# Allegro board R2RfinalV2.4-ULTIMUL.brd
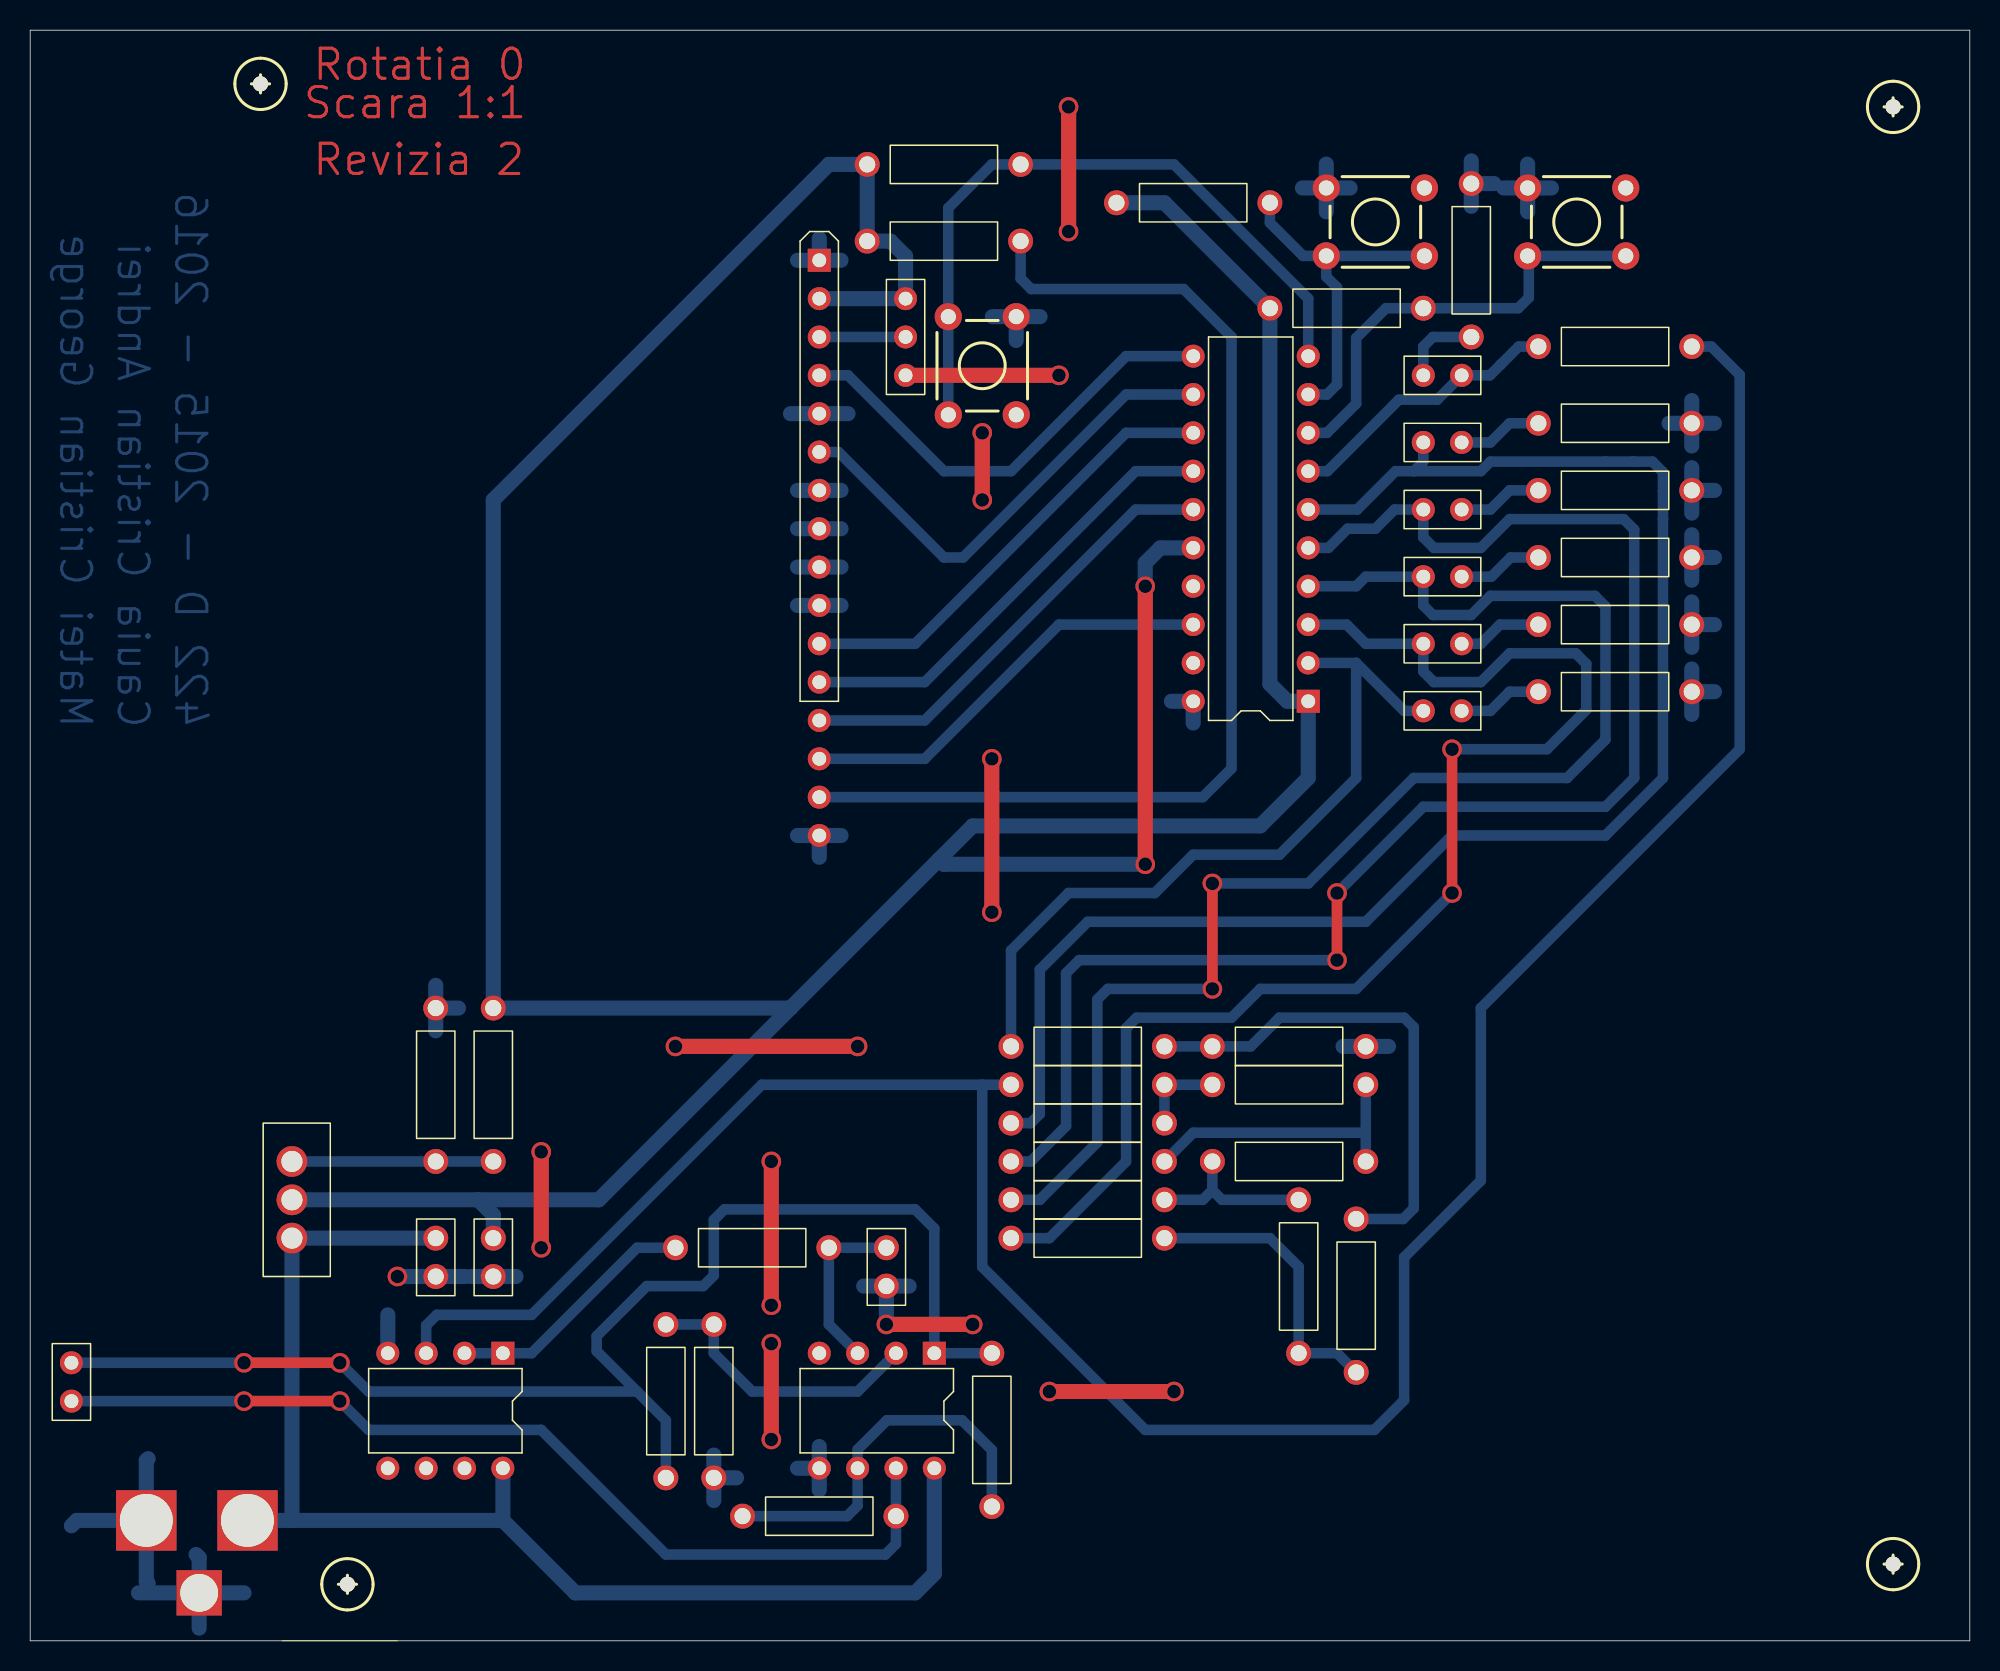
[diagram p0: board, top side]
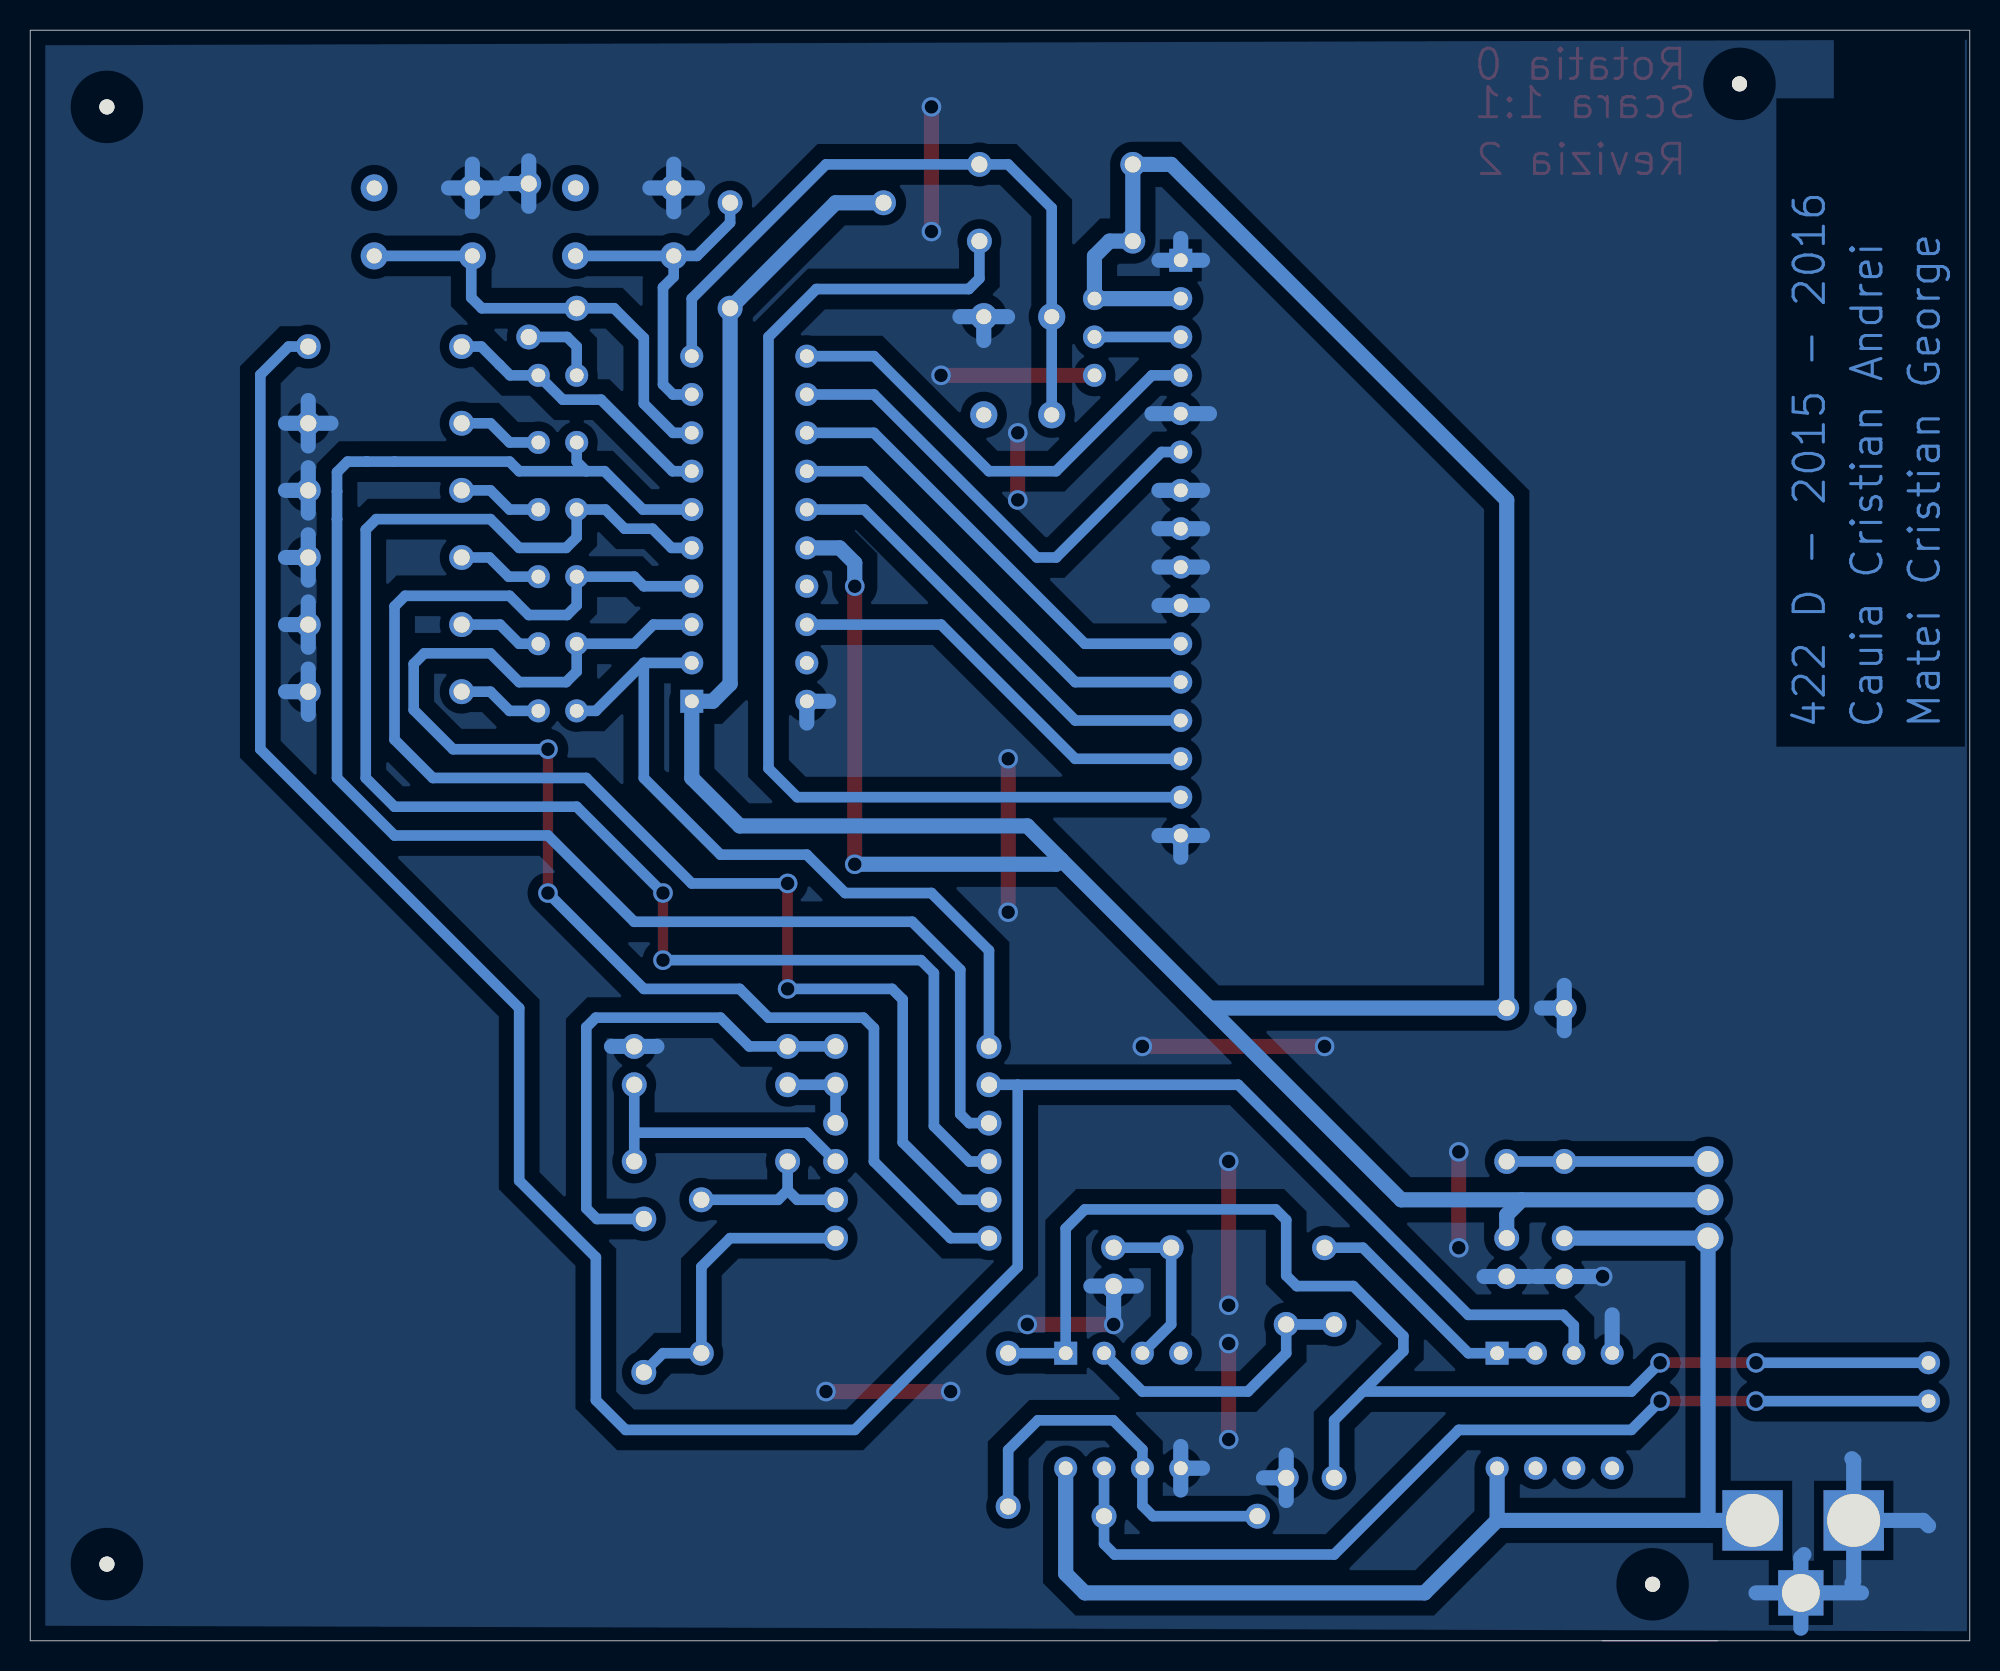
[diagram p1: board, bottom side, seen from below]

Outline 128.46 x 106.68 mm; copper layers: TOP, BOTTOM. Coordinates in mm from the lower left corner of the outline.
Outline path: 24.32,0 0,0 0,106.68 128.46,106.68 128.46,0 16.7,0

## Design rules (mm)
net group VCC: nets N20855 N35721 SW1 SW2 SW3 VCC
nets with their own width: min track width 0.7; nets N00328 N00336 N00340 N00355 N00395 N00470 N01662 N01669 N01683 N01690 N01717 N006340 N006500 N006660 N006820 N006980 N007140 N23488 N23661 N24189 N24193 N25824 N25853 N29134 N35057 N35516 N35592 N35638 N35656 N35674 N35692
nets with their own width: min track width 1; nets 0 9V

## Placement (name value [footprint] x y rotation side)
C3  10nf  [CAPCK05]  56.7 26.04 180 top
C4  10u  [CAPCK05]  26.86 24.13 0 top
C5  10u  [CAPCK05]  30.67 24.13 0 top
D1  MLED81  [JUMPER2]  94.81 83.82 180 top
D2  MLED81  [JUMPER2]  92.26 79.38 0 top
D3  MLED81  [JUMPER2]  92.26 74.93 0 top
D4  MLED81  [JUMPER2]  92.26 70.49 0 top
D5  MLED81  [JUMPER2]  92.26 66.04 0 top
D6  MLED81  [JUMPER2]  92.26 61.6 0 top
J1  Speaker  [JUMPER2]  2.73 18.42 270 top
J2  LCD 1602  [SIP16]  52.26 91.44 0 top
J3  CON3  [JACK_DC2]  0.19 3.18 0 top
NOREF  -  [unnamed]  123.38 101.6 0 top
NOREF#2  -  [unnamed]  15.25 103.13 0 top
NOREF#3  -  [unnamed]  21.01 3.74 0 top
NOREF#4  -  [unnamed]  123.38 5.08 0 top
R2  1k  [RES400]  75.12 36.83 90 top
R3  1k  [RES400]  88.45 36.83 90 top
R4  1k  [RES400]  78.3 31.75 270 top
R5  1k  [RES400]  84.01 19.05 0 top
R6  1k  [RES400]  87.82 27.94 180 top
R7  2k  [RES400]  64.96 39.37 270 top
R8  2k  [RES400]  64.96 26.67 270 top
R9  2k  [RES400]  64.96 29.21 270 top
R10  2k  [RES400]  64.96 31.75 270 top
R11  2k  [RES400]  64.96 34.29 270 top
R12  2k  [RES400]  99.88 85.73 270 top
R13  2k  [RES400]  88.45 39.37 90 top
R14  470  [RES400]  110.05 62.87 90 top
R15  470  [RES400]  110.05 67.31 90 top
R16  470  [RES400]  110.05 71.75 90 top
R17  470  [RES400]  110.05 76.2 90 top
R18  470  [RES400]  110.05 80.65 90 top
R19  470  [RES400]  95.44 96.52 180 top
R20  10k  [RES400]  45.27 20.96 180 top
R22  10k  [RES400]  63.69 8.89 0 top
R23  1k  [RES400]  26.86 41.91 180 top
R24  470  [RES400]  30.67 31.75 0 top
R26  33k  [RES400]  42.74 26.04 270 top
R27  10k  [RES400]  42.1 10.8 0 top
R28  10k  [RES400]  57.34 8.25 90 top
R29  1k  [JUMPER3]  57.98 83.82 90 top
R30  10k  [RES400]  65.6 97.79 90 top
R33  1k  [RES400]  55.44 92.71 270 top
R34  10k  [RES400]  82.11 95.25 90 top
R35  10k  [RES400]  92.26 88.27 90 top
SW7  SW_TC_SPST  [SW_SCHURTER_13019306L]  63.06 84.46 0 top
SW8  SW_TC_SPST  [SW_SCHURTER_13019306L]  89.09 93.98 90 top
SW9  SW_TC_SPST  [SW_SCHURTER_13019306L]  102.43 93.98 90 top
U1  MSP430G2553  [DIP20]  84.64 62.23 180 top
U7  LM317K  [TO220AB]  17.33 31.75 90 top
U9  LM358  [DIP8_3]  59.88 19.05 270 top
U10  LM358  [DIP8_3]  31.31 19.05 270 top

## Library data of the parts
C3 = C: Tolerance: ***; User Part Number: ***; signal model: DEFAULT_CAPACITOR_10000pF_1_2
C4 C5 = C: Tolerance: ***; User Part Number: ***; signal model: DEFAULT_CAPACITOR_1e+07pF_1_2
D1-D6 = MLED81: User Part Number: ***
J1 = CON2: User Part Number: ***
J2 = CON16: User Part Number: ***
J3 = CON3
R2-R6 R23 R33 = R: Tolerance: ***; User Part Number: ***; signal model: DEFAULT_RESISTOR_1000OHM_2_1
R7-R13 = R: Tolerance: ***; User Part Number: ***; signal model: DEFAULT_RESISTOR_2000OHM_2_1
R14-R19 R24 = R: Tolerance: ***; User Part Number: ***; signal model: DEFAULT_RESISTOR_470OHM_2_1
R20 R22 R27 R28 R30 R34 R35 = R: Tolerance: ***; User Part Number: ***; signal model: DEFAULT_RESISTOR_10000OHM_2_1
R26 = R: Tolerance: ***; User Part Number: ***; signal model: DEFAULT_RESISTOR_33000OHM_2_1
R29 = POT: User Part Number: ***
SW7-SW9 = SW_TC_SPST
U1 = MSP430G2553_4: Tolerance: ***; User Part Number: ***
U7 = LM317T_0
U9 = LM358: Tolerance: ***; User Part Number: ***
U10 = LM358_0: Tolerance: ***; User Part Number: ***

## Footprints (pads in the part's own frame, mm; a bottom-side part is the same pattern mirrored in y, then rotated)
CAPCK05
  round 1.651 hole 1.067: 1(0,0) 2(0,2.54)
DIP8_3
  rect 1.524x1.524 hole 0.914: 1(0,0)
  round 1.524 hole 0.914: 2(0,-2.54) 3(0,-5.08) 4(0,-7.62) 5(7.62,-7.62) 6(7.62,-5.08) 7(7.62,-2.54) 8(7.62,0)
DIP20
  rect 1.524x1.524 hole 0.914: 1(0,0)
  round 1.524 hole 0.914: 2(0,-2.54) 3(0,-5.08) 4(0,-7.62) 5(0,-10.16) 6(0,-12.7) 7(0,-15.24) 8(0,-17.78) 9(0,-20.32) 10(0,-22.86) 11(7.62,-22.86) 12(7.62,-20.32) 13(7.62,-17.78) 14(7.62,-15.24) 15(7.62,-12.7) 16(7.62,-10.16) 17(7.62,-7.62) 18(7.62,-5.08) 19(7.62,-2.54) 20(7.62,0)
JACK_DC2
  rect 4x4 hole 3.5: 1(14.2,4.8) 2(7.5,4.8)
  rect 3x3 hole 2.5: 3(11,0)
JUMPER2
  round 1.524 hole 0.914: 1(0,0) 2(2.54,0)
JUMPER3
  round 1.524 hole 0.914: 1(0,0) 2(2.54,0) 3(5.08,0)
RES400
  round 1.651 hole 1.067: 1(0,0) 2(0,10.16)
SIP16
  rect 1.524x1.524 hole 0.914: 1(0,0)
  round 1.524 hole 0.914: 2(0,-2.54) 3(0,-5.08) 4(0,-7.62) 5(0,-10.16) 6(0,-12.7) 7(0,-15.24) 8(0,-17.78) 9(0,-20.32) 10(0,-22.86) 11(0,-25.4) 12(0,-27.94) 13(0,-30.48) 14(0,-33.02) 15(0,-35.56) 16(0,-38.1)
SW_SCHURTER_13019306L
  round 1.8 hole 1: 1(-2.25,-3.25) 2(-2.25,3.25) 3(2.25,3.25) 4(2.25,-3.25)
TO220AB
  round 2.032 hole 1.397: 1(0,0) 2(-2.54,0) 3(-5.08,0)
unnamed
  round 1 hole 3.2 unplated: (0,0)

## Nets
9V: C4.2 J3.1 U7.3(OUT) U9.8(V+) U10.8(V+)
VCC: C5.2 J2.2 R24.2 R29.3(2) R30.2 R33.1 R34.2 R35.2 U1.1(DVCC) U1.16(RESET) U7.2(IN)
0: C3.2 C4.1 C5.1 J2.1 J2.5 J2.7 J2.8 J2.9 J2.10 J2.16 J3.2 J3.3 R13.1 R14.1 R15.1 R16.1 R17.1 R18.1 R19.1 R20.2 R23.1 R29.1 SW7.3 SW8.3 SW9.3 U1.20(GROUND) U9.4(V-) U9.5(+) U10.4(V-)
SW1: R30.1 SW7.1 SW7.2 U1.10(P2_2)
SW2: R34.1 SW8.1 SW8.2 U1.9(P2_1)
SW3: R35.1 SW9.1 SW9.2 U1.8(P2_0/CS(B0))
N00328: R2.1 R3.2 R11.2
N00336: R4.1 R5.2 R9.2
N00340: R5.1 R6.2 R8.2
N00355: R2.2 R12.2 U10.3(+)
N00395: R3.1 R4.2 R10.2
N00470: R6.1 R7.2 R13.2
N01662: D5.1(A) R8.1 U1.3(P1_1/A1/RXD)
N01669: D4.1(A) R9.1 U1.4(P1_2/A2/TXD)
N01683: D2.1(A) R11.1 U1.6(P1_4/A4)
N01690: D1.1(A) R12.1 U1.7(P1_5/A5/SCK(B0))
N01717: D3.1(A) R10.1 U1.5(P1_3/A3/PUSH2)
N006340: D6.2(C) R14.2
N006500: D5.2(C) R15.2
N006660: D4.2(C) R16.2
N006820: D3.2(C) R17.2
N006980: D2.2(C) R18.2
N007140: D1.2(C) R19.2
N20855: R23.2 R24.1 U7.1(ADJ)
N23488: C3.1 R26.2 U9.3(+)
N23661: R26.1 U10.1(OUT) U10.2(-)
N24189: R20.1 R27.2 U9.2(-)
N24193: J1.1 R22.2 R27.1 U9.1(OUT)
N25824: R22.1 R28.2 U9.6(-)
N25853: J1.2 R28.1 U9.7(OUT)
N29134: D6.1(A) R7.1 U1.2(P1_0/A0/RED_LED)
N35057: J2.3 R29.2(T)
N35516: J2.4 U1.11(P2_3)
N35592: J2.6 U1.12(P2_4)
N35638: J2.11 U1.13(P2_5)
N35656: J2.12 U1.14(P1_6/A6/SCL/MISO(B0)/GREEN LED)
N35674: J2.13 U1.15(P1_7/A7/SDA/MOSE(B0))
N35692: J2.14 U1.18(P2_7/XOUT)
N35721: J2.15 R33.2

Pads without a net: SW7 4; SW8 4; SW9 4; U1 17 19; U10 5 6 7

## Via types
v1: diameter 1.3, hole 0.9, TOP to BOTTOM, 32 vias

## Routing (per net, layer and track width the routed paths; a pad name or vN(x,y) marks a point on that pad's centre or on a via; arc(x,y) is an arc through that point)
9V: length 86.7
  BOTTOM w1: U10.8 31.31,7.98 ; 31.31,7.98 36.11,3.18 58.61,3.18 59.88,4.44 U9.8 ; 31.31,7.98 17.33,7.98 ; C4.2 U7.3 17.33,7.98 ; 17.33,7.98 J3.1
VCC: length 269.1
  TOP w1: v1(73.85,69.85) v1(73.85,51.44)
  BOTTOM w1: 60.2,51.75 60.52,51.44 v1(73.85,51.44) ; 60.2,51.75 62.42,53.98 81.47,53.98 84.64,57.15 U1.1 83.26,62.23 82.11,63.38 R35.2 75.12,95.25 R34.2 ; 60.2,51.75 50.36,41.91 ; J2.2 R29.3 57.98,91.71 56.98,92.71 R33.1 R30.2 52.89,97.79 30.67,75.56 R24.2 50.36,41.91 ; 50.36,41.91 37.65,29.21 29.67,29.21 ; 29.67,29.21 30.67,28.21 C5.2 ; 29.67,29.21 U7.2 ; U1.16 74.85,72.39 73.85,71.39 v1(73.85,69.85)
0: length 211.5
  TOP w1: 58.05,83.75 R29.1 v1(68.13,83.82) ; v1(68.77,93.35) v1(68.77,101.6) ; v1(54.8,39.37) v1(42.74,39.37) ; v1(75.75,16.51) v1(67.5,16.51) ; v1(33.85,26.04) v1(33.85,32.38) ; v1(49.08,22.23) v1(49.08,31.75) ; v1(49.08,19.69) v1(49.08,13.34) ; v1(56.7,20.96) v1(62.42,20.96) ; v1(63.69,48.26) v1(63.69,58.42) ; v1(63.06,75.56) v1(63.06,80.01)
  BOTTOM w1: 110.05,70.25 R16.1 ; R16.1 110.05,73.26 ; R16.1 111.55,71.75 ; 28.76,24.13 C4.1 v1(24.32,24.13) ; 29.17,24.13 C5.1 32.17,24.13 ; 26.86,40.41 R23.1 ; R23.1 26.86,43.41 ; R23.1 28.36,41.91 ; SW9.3 100.75,96.23 ; SW9.3 99.18,97.81 ; SW9.3 97.6,96.23 ; SW9.3 99.18,94.65 ; v1(56.7,20.96) C3.2 ; C3.2 55.2,23.5 ; C3.2 58.21,23.5 ; J3.3 11.19,5.51 10.99,5.72 ; J3.3 11.19,0.84 ; J3.3 14.16,3.18 ; J3.3 7.18,3.18 ; 110.05,65.81 R15.1 ; R15.1 111.55,67.31 ; R15.1 110.05,68.81 ; 50.82,68.58 J2.10 53.7,68.58 ; 110.05,61.36 R14.1 ; R14.1 111.55,62.87 ; R14.1 110.05,64.37 ; 50.82,73.66 J2.8 53.7,73.66 ; 50.82,53.34 J2.16 ; J2.16 52.26,51.9 ; J2.16 53.7,53.34 ; R18.1 111.55,80.65 ; R18.1 110.05,79.14 ; R18.1 110.05,82.15 ; R18.1 108.54,80.65 ; 53.7,76.2 J2.7 50.82,76.2 ; 84.26,96.23 SW8.3 ; SW8.3 87.42,96.23 ; SW8.3 85.84,97.81 ; SW8.3 85.84,94.65 ; R17.1 111.55,76.2 ; R17.1 110.05,74.7 ; R17.1 110.05,77.7 ; 45.27,9.29 R20.2 ; R20.2 46.78,10.8 ; R20.2 45.27,12.3 ; 86.95,39.37 R13.1 89.96,39.37 ; 54.17,81.28 J2.5 50.36,81.28 ; U9.5 52.26,12.87 ; U9.5 50.82,11.43 ; U9.5 52.26,9.99 ; 95.44,95.02 R19.1 ; R19.1 95.44,98.02 ; R19.1 96.94,96.52 ; J3.2 7.69,3.93 7.81,3.81 ; J3.2 7.69,11.94 7.81,12.06 ; J3.2 3.09,7.98 2.73,7.62 ; 75.58,62.23 U1.20 77.02,60.79 ; J2.1 52.26,92.88 ; J2.1 50.82,91.44 ; J2.1 53.7,91.44 ; 63.73,87.71 SW7.3 ; SW7.3 65.31,86.13 ; SW7.3 66.88,87.71 ; U10.4 23.69,21.59 ; 53.7,71.12 J2.9 50.82,71.12
SW1: length 46.2
  BOTTOM w0.7: U1.10 84.64,88.9 75.75,97.79 R30.1 63.69,97.79 60.81,94.91 SW7.2 SW7.1
SW2: length 23.5
  BOTTOM w0.7: SW8.2 85.84,90.35 86.55,89.64 86.55,83.22 85.88,82.55 U1.9 ; SW8.2 SW8.1 ; SW8.2 84.3,91.73 82.11,93.93 R34.1
SW3: length 30.2
  BOTTOM w0.7: U1.8 85.88,80.01 87.82,81.95 87.82,86.3 89.79,88.27 R35.1 98.55,88.27 99.25,88.97 99.25,91.66 SW9.2 SW9.1
N00328: length 5.7
  BOTTOM w0.7: R11.2 R2.1 78.3,36.83
N00336: length 11.3
  BOTTOM w0.7: R4.1 78.3,29.85 ; 78.3,29.85 78.93,29.21 R5.2 ; 78.3,29.85 77.66,29.21 R9.2
N00340: length 19.7
  BOTTOM w0.7: R6.2 86.55,19.05 R5.1 84.01,24.77 82.11,26.67 R8.2
N00355: length 173.5
  BOTTOM w0.7: 63.06,36.83 48.45,36.83 33.21,21.59 26.93,21.59 26.23,20.89 U10.3 ; 63.06,36.83 63.06,24.77 73.85,13.97 89.02,13.97 91,15.94 91,25.4 96.07,30.48 96.07,41.91 113.22,59.06 113.22,83.85 111.35,85.73 R12.2 ; 63.06,36.83 R2.2
N00395: length 19.2
  BOTTOM w0.7: 88.45,33.66 77.02,33.66 R10.2 ; 88.45,33.66 R4.2 ; 88.45,33.66 R3.1
N00470: length 33.7
  BOTTOM w0.7: R7.2 80.83,39.37 82.74,41.28 91,41.28 91.63,40.64 91.63,28.64 90.93,27.94 R6.1
N01662: length 88.5
  TOP w0.7: v1(94.17,49.53) v1(94.17,59.06)
  BOTTOM w0.7: U1.3 87.19,67.31 88.45,66.04 D5.1 92.26,64.2 92.96,63.5 96.07,63.5 97.98,65.41 102.36,65.41 103.06,64.71 103.06,61.66 100.45,59.06 v1(94.17,59.06) ; R8.1 67.5,26.67 72.58,31.75 72.58,40.57 73.28,41.28 79.56,41.28 81.47,43.18 87.82,43.18 v1(94.17,49.53)
N01669: length 93.4
  TOP w0.7: v1(78.3,43.18) v1(78.3,50.17)
  BOTTOM w0.7: v1(78.3,50.17) 84.64,50.17 91.63,57.15 101.79,57.15 104.33,59.69 104.33,68.52 103.63,69.22 96.71,69.22 95.44,67.94 92.9,67.94 92.26,68.58 D4.1 88.45,70.49 87.82,69.85 U1.4 ; v1(78.3,43.18) 71.38,43.18 70.68,42.48 70.68,33.02 66.87,29.21 R9.1
N01683: length 105.8
  BOTTOM w0.7: 91.63,77.47 96.07,77.47 96.71,78.11 104.33,78.11 106.17,78.1 107.44,78.1 108.14,77.4 108.14,76.14 108.14,74.3 108.14,57.15 104.33,53.34 94.17,53.34 88.45,47.62 70.04,47.62 66.87,44.45 66.87,34.89 66.26,34.29 R11.1 ; 91.63,77.47 90.43,77.47 87.88,74.93 U1.6 ; 91.63,77.47 92.26,78.11 D2.1
N01690: length 18.7
  BOTTOM w0.7: U1.7 85.92,77.47 90.65,82.21 93.19,82.21 D1.1 96.68,83.82 97.38,84.52 98.58,85.73 R12.1
N01717: length 102.6
  TOP w0.7: v1(86.55,45.09) v1(86.55,49.53)
  BOTTOM w0.7: R10.1 66.26,31.75 68.61,34.1 68.61,44.22 69.47,45.09 v1(86.55,45.09) ; U1.5 85.98,72.39 87.25,73.66 89.09,73.66 90.36,74.93 D3.1 92.26,73.09 92.96,72.39 96.07,72.39 97.98,74.3 105.54,74.3 106.24,73.6 106.24,57.15 104.33,55.25 92.26,55.25 v1(86.55,49.53)
N006340: length 5.6
  BOTTOM w0.7: R14.2 97.98,62.87 96.71,61.6 D6.2
N006500: length 5.6
  BOTTOM w0.7: R15.2 97.35,67.31 96.07,66.04 D5.2
N006660: length 5.6
  BOTTOM w0.7: D4.2 96.77,70.49 98.05,71.75 R16.2
N006820: length 5.6
  BOTTOM w0.7: D3.2 96.71,74.93 97.98,76.2 R17.2
N006980: length 5.6
  BOTTOM w0.7: R18.2 97.98,80.65 96.71,79.38 D2.2
N007140: length 5.3
  BOTTOM w0.7: R19.2 92.9,86.36 92.26,85.73 D1.2
N20855: length 13.3
  BOTTOM w0.7: U7.1 R23.2 R24.1
N23488: length 11.6
  BOTTOM w0.7: C3.1 R26.2 52.89,20.96 U9.3
N23661: length 16.9
  BOTTOM w0.7: R26.1 40.19,26.04 33.21,19.05 U10.1 U10.2
N24189: length 19.2
  BOTTOM w0.7: U9.2 54.8,16.51 47.81,16.51 45.27,19.05 R20.1 R27.2
N24193: length 90.1
  TOP w0.7: v1(20.51,18.42) v1(14.16,18.42)
  BOTTOM w0.7: R27.1 42.1,14.61 40.19,16.51 ; R22.2 U9.1 59.88,27.31 58.61,28.57 45.98,28.57 45.27,27.88 45.27,24.19 44.57,23.5 40.83,23.5 37.51,20.18 37.51,19.19 40.19,16.51 ; v1(20.51,18.42) 22.41,16.51 40.19,16.51 ; v1(14.16,18.42) J1.1
N25824: length 25.9
  BOTTOM w0.7: R22.1 63.69,12.63 61.72,14.61 56.74,14.61 54.8,12.67 U9.6 54.8,8.96 54.1,8.25 R28.2
N25853: length 64.1
  TOP w0.7: v1(20.51,15.88) v1(14.16,15.88)
  BOTTOM w0.7: U9.7 R28.1 57.34,6.42 56.64,5.72 42.1,5.72 33.85,13.97 22.42,13.97 v1(20.51,15.88) ; v1(14.16,15.88) J1.2
N29134: length 50.5
  BOTTOM w0.7: 87.82,64.77 87.82,57.15 82.74,52.07 77.02,52.07 74.49,49.53 68.77,49.53 64.96,45.72 R7.1 ; 87.82,64.77 91,61.6 D6.1 ; 87.82,64.77 U1.2
N35057: length 5.7
  BOTTOM w0.7: J2.3 R29.2
N35516: length 30.6
  BOTTOM w0.7: J2.4 54.17,83.82 60.51,77.47 64.96,77.47 72.58,85.09 U1.11
N35592: length 32.1
  BOTTOM w0.7: J2.6 53.53,78.74 60.51,71.75 61.79,71.75 72.58,82.55 U1.12
N35638: length 30.6
  BOTTOM w0.7: J2.11 58.61,66.04 72.58,80.01 U1.13
N35656: length 30.6
  BOTTOM w0.7: J2.12 59.25,63.5 73.21,77.47 U1.14
N35674: length 30.6
  BOTTOM w0.7: U1.15 73.21,74.93 59.25,60.96 J2.13
N35692: length 28.4
  BOTTOM w0.7: J2.14 59.25,58.42 68.13,67.31 U1.18
N35721: length 74.7
  BOTTOM w0.7: R33.2 65.6,90.24 66.3,89.54 76.39,89.54 79.56,86.36 79.56,57.79 77.66,55.88 J2.15

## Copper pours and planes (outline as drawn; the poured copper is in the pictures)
0 on BOTTOM: 0.19,0.63 0.19,106.05 127.46,105.68 127.46,1

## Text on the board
BOTTOM: Matei Cristian George | Cauia Cristian Andrei | 422 D - 2015 - 2016
TOP: Scara 1:1 | Rotatia 0 | Revizia 2
PAGE_OUTLINE: Scara 1:1 | Rotatia 0 | Revizia 1 | Fabrication | Matei Cristian George | Cauia Cristian Andrei | Grupa 422D 2015 - 2016
DISPLAY_TOP: FIGURE | SIZE | 0.9 | 0.9144 | 1.0 | 1.0668 | 1.397 | 2.5001 | 3.5001 | 3.2 | DRILL CHART: TOP to BOTTOM | ALL UNITS ARE IN MILLIMETERS | PLATED | NON-PLATED | QTY | 34 | 69 | 12 | 64 | 3 | 1 | 2 | 4
